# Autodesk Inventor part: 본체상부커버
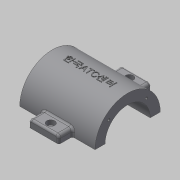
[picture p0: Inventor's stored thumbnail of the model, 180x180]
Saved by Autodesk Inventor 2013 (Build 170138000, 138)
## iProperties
Created: 2015-12
Part Number: 본체상부커버
Material: 일반
Document SubType Name: Modeling
Designer: mduedu
Density: 1 g/cm^3
Mass: 70.1561 g
Surface Area: 187.8 cm^2
Volume: 70.1561 cm^3
Author: mduedu
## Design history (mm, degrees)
sketch "스케치1"
  geometry: L1 (45, 40)-(-45, 40); L2 (-45, 40)-(-45, -40); L3 (-45, -40)-(45, -40); L4 (45, -40)-(45, 40); L5 (45, 40)-(-45, -40); L6 (-45, 40)-(45, -40); 2 further points
  constraints: 12 end point, 2 midpoint, 2 parallel, 1 coincident, 1 horizontal, 1 perpendicular, 3 other
  dimensions: "d0" = 90 distance of L2.end L3.end; "d2" = 80 distance of L1.end L2.end
extrude "돌출1" new body sketch "스케치1" distance "d3" = 10; taper "d4" = 0 deg
sketch "스케치2"
  geometry: C1 r 32.5 at (80, 0); 1 further point
  constraints: 1 centre point
  dimensions: "d5" = 65 diameter of C1; "d116" = 80 distance of point (0, 0) C1.centre
extrude "돌출2" join sketch "스케치2" stored distance "d7" = 75; taper "d8" = 0 deg
sketch "스케치3"
  geometry: L1 (-27.5, -20)-(27.5, -20); L2 (27.5, -20)-(27.5, 20); L3 (27.5, 20)-(-27.5, 20); L4 (-27.5, 20)-(-27.5, -20); L5 (-27.5, -20)-(27.5, 20); L6 (27.5, -20)-(-27.5, 20); 1 further point
  constraints: 12 end point, 2 midpoint, 2 parallel, 1 horizontal, 1 perpendicular
  dimensions: "d9" = 55 distance of L2.end L3.end; "d11" = 40 distance of L1.end L2.end
extrude "돌출3" new body sketch "스케치3" stored distance "d12" = 75; taper "d13" = 0 deg
fillet "모깎기1"
fillet "모깎기2"
feature "결합1"
  node "솔리드2"
sketch "스케치4"
  geometry: L1 (-37.5, 47.5)-(37.5, 47.5) reference; L2 (32.5, 47.5)-(40.208, 10); L3 (37.5, 47.5)-(37.5, 112.5) reference; L4 (60.208, 0)-(60.208, 10) reference; L5 (60.208, 10)-(-60.208, 10) reference; 1 further point
  constraints: 2 end point, 2 point on line
  dimensions: "d15" = 5 distance from line of L2.start L3; "d117" = 20 distance from line of L2.end L4
sketch "스케치5"
  geometry: L1 (10, 35.208)-(56.729, 22.687); L2 (0, 60.208)-(10, 60.208) reference; L3 (10, -60.208)-(10, 60.208) reference; 2 further points
  constraints: 2 end point, 1 point on line, 2 other
  dimensions: "d118" = 25 distance from line of L1.start L2; "d119" = 75 deg angle of L1 L3
feature "리브1" dims "d19" = 1, "d20" = 6, "d21" = 0, "d22" = 0, "d23" = 1, "d24" = 1
feature "리브2" dims "d25" = 1, "d26" = 6, "d27" = 0, "d28" = 0, "d29" = 1, "d30" = 1
fillet "모깎기4" dims "d31" = 2
fillet "모깎기5" dims "d32" = 2
fillet "모깎기6" dims "d33" = 2
sketch "스케치6"
  geometry: L1 (0, 0)-(-32.88, 32.88); L2 (0, 0)-(-46.5, 0); A1 r 46.5 centre (0, 0) between (-32.88, 32.88) and (-46.5, 0); 5 further points
  constraints: 4 end point, 2 coincident, 2 point on circle, 1 centre point, 1 horizontal, 5 other
  dimensions: "d120" = 93 diameter of A1; "d122" = 45 deg angle of L1 L2; "d126" = 360 deg dimension on point (0, 0) point (-32.88, 32.88) (derived)
hole "구멍1" sketch "스케치6" at (-32.88, 32.88), (-32.88, -32.88), (32.88, -32.88), (32.88, 32.88) diameter "d34" = 7; stored, may be unused: countersink angle "d38" = 90 deg, drill point angle "d40" = 118 deg; dims "d35" = 6, "d36" = 12, "d37" = 3, "d39" = 8
fillet "모깎기13" dims "d131" = 3
hole "구멍2" diameter "d44" = 45; stored, may be unused: countersink angle "d48" = 90 deg, drill point angle "d50" = 118 deg; dims "d42" = 10, "d43" = 10, "d45" = 6, "d46" = 4, "d47" = 2, "d49" = 8
sketch "스케치7" dims "d52" = 26.5
  geometry: L1 (0, 0)-(32.5, 0); L2 (0, 0)-(22.981, 22.981); A1 r 32.5 centre (0, 0) between (32.5, 0) and (22.981, 22.981) reference; 3 further points
  constraints: 4 end point, 2 point on circle, 1 coincident, 1 horizontal, 1 point on line, 3 other
  dimensions: "d51" = 45 deg angle of L2 L1
hole "구멍3" sketch "스케치7" at (18.738, 18.738) diameter "d54" = 2.459; stored, may be unused: countersink angle "d58" = 90 deg, drill point angle "d60" = 118 deg; dims "d55" = 8, "d56" = 4, "d57" = 2, "d59" = 10
sketch "스케치8"
  geometry: L1 (72.5, 31.623)-(72.5, 46); L2 (72.5, 46)-(87.5, 46); L3 (87.5, 46)-(87.5, 31.623); A1 r 32.5 centre (80, 0) between (87.5, 31.623) and (72.5, 31.623) reference; 2 further points
  constraints: 6 end point, 2 point on circle, 1 horizontal, 1 midpoint, 1 parallel, 1 vertical, 1 vertical alignment
  dimensions: "d64" = 15 distance of L1.end L2.end; "d66" = 46 distance from line of L2 A1.centre
extrude "돌출4" join sketch "스케치8" stored distance "d67" = 30; taper "d68" = 0 deg
fillet "모깎기8" dims "d69" = 3
fillet "모깎기9" dims "d70" = 2
node "작업 평면2"
sketch "스케치16"
  geometry: L1 (33.166, 72.5)-(44, 72.5) reference; L2 (42.5, 72.5)-(28.53, 64.434); L3 (46, 75.5)-(46, 84.5) reference; 2 further points
  constraints: 2 end point, 1 point on line, 2 other
  dimensions: "d138" = 30 deg angle of L2 L1; "d139" = 3.5 distance from line of L2.start L3
feature "리브3" sketch "스케치16" dims "d140" = 1, "d141" = 3, "d142" = 0, "d143" = 0, "d144" = 1, "d145" = 1
fillet "모깎기14" dims "d146" = 1
fillet "모깎기15" dims "d147" = 1
sketch "스케치9"
  geometry: L1 (-76, -110)-(76, -110); L2 (76, -110)-(76, 0); L3 (76, 0)-(-76, 0); L4 (-76, 0)-(-76, -110); L5 (-46, 4.5)-(-46, -4.5) reference; L6 (-60.208, -80)-(60.208, -80) reference; C1 r 32.5 at (0, 0) reference; 2 further points
  constraints: 8 end point, 2 parallel, 1 coincident, 1 horizontal, 1 midpoint, 1 perpendicular
  dimensions: "d72" = 30 distance between parallel lines of L4 L5; "d148" = 30 distance between parallel lines of L6 L1
extrude "돌출5" cut sketch "스케치9" stored distance "d73" = 0; taper "d74" = 0 deg
node "작업 평면3"
sketch "스케치17"
  geometry: 2 further points
  constraints: 1 coincident, 1 other
feature "엠보싱1" sketch "스케치17" dims "d12" = 75, "d13" = 0, "d150" = 0.5, "d151" = 0
sketch "스케치18"
  geometry: L1 (-3, -1.039)-(-3, -10.834) reference; L2 (27, -10.834)-(27, -1.039) reference; L3 (0, -12.834)-(24, -12.834) reference; L4 (-3, -5.936)-(27, -5.936); L5 (12, -12.834)-(12, 33.166); 1 further point
  constraints: 4 end point, 4 midpoint, 1 perpendicular, 1 point on line
hole "구멍8" sketch "스케치18" at (12, -5.936) diameter "d152" = 4.5; stored, may be unused: countersink angle "d156" = 90 deg, drill point angle "d158" = 118 deg; dims "d153" = 6, "d154" = 8, "d155" = 4.6, "d157" = 8
node "솔리드1"
mirror "대칭1"
mirror "대칭2"
pattern_circular "원형 패턴1" dims angle "d62" = 360 deg
mirror "대칭3"
mirror "대칭7"
mirror "대칭4"
mirror "대칭8"
other parameters: "d137" = -5
